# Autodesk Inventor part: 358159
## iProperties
Created: 2006-10
Part Number: 358159
Material: 1.0718.07
Description: Rolle
Document SubType Name: Modeling
Designer: OSchmidt
Density: 7.84 g/cm^3
Abmessung: Rd. 30
HalbzeugNorm: DIN 671
Zweck: 266461
Author: Natti_01
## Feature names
1. Extrusion1
2. Fase1 [Chamfer]
